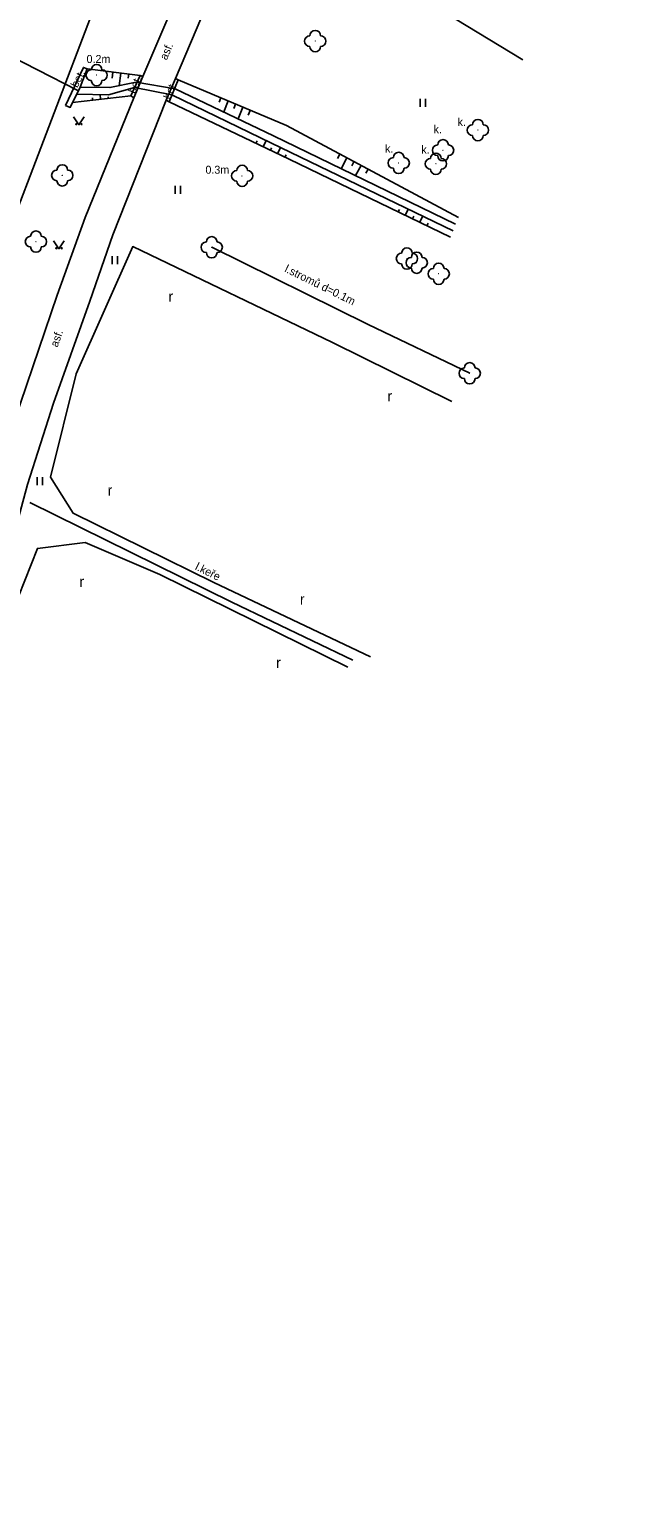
# Model space of a CAD drawing. Extents: x -544674 to -541478, y -1199076 to -1195527.
# Drawn here: x -543771.7 to -543714.9, y -1196778.9 to -1196641.1 of the extents above; entities that cross this region are included whole.
import ezdxf

# ---------------------------------------------------------------- set-up
doc = ezdxf.new("R2010")
doc.units = 0
for name, color, linetype in [('POMOC_POPIS', 7, 'Continuous'), ('ROZHRANÍ_PLOCH', 7, 'Continuous'), ('VÝŠKOPIS', 7, 'Continuous'), ('ZELEŇ', 7, 'Continuous'), ('ZN_DOPLŇKOVÉ', 7, 'Continuous'), ('ZN_KULTUR', 7, 'Continuous')]:
    doc.layers.add(name, color=color, linetype=linetype)

msp = doc.modelspace()

# ---------------------------------------------------------------- linework, layer by layer
at = {"layer": 'ROZHRANÍ_PLOCH'}
for points in [[(-543807.06, -1196806.28), (-543806.75, -1196807.49), (-543805.62, -1196808.57), (-543803.6, -1196809.36), (-543801.75, -1196808.81), (-543800.5, -1196806.91), (-543795.65, -1196782.4), (-543789.39, -1196750.31), (-543785.15, -1196728.76), (-543782.4, -1196714.76), (-543781.01, -1196708.01), (-543777.88, -1196694.39), (-543774.44, -1196682.01), (-543772.54, -1196676.07), (-543769.09, -1196665.96), (-543766.47, -1196658.69), (-543761.92, -1196647.47), (-543762.18, -1196647.29), (-543761.3, -1196645.37), (-543761.06, -1196645.47), (-543756.75, -1196635.37), (-543752.77, -1196625.68), (-543747.9, -1196614.82)], [(-543774.29, -1196661.75), (-543765.48, -1196638.63), (-543761.91, -1196630.37)], [(-543792.85, -1196784.15), (-543786.36, -1196750.19), (-543782.23, -1196728.89), (-543779.59, -1196715.45), (-543778.13, -1196707.91), (-543774.74, -1196694.16), (-543771.89, -1196683.71), (-543769.45, -1196676.08), (-543766.05, -1196666.53), (-543763.87, -1196660.3), (-543758.86, -1196647.68), (-543758.58, -1196647.85), (-543757.75, -1196645.78), (-543758, -1196645.66), (-543754.11, -1196636.49)], [(-543768.32, -1196648.19), (-543767.87, -1196648.36), (-543767.66, -1196647.89), (-543767.26, -1196647.12), (-543766.93, -1196646.48), (-543766.29, -1196644.75), (-543766.63, -1196644.61), (-543768.32, -1196648.19)], [(-543761.06, -1196645.47), (-543761.92, -1196647.47)], [(-543758.86, -1196647.68), (-543758, -1196645.66)]]:
    msp.add_lwpolyline(points, dxfattribs=at)
at = {"layer": 'VÝŠKOPIS'}
for points in [[(-543761.3, -1196645.37), (-543766.29, -1196644.75)], [(-543763.88, -1196645.05), (-543763.95, -1196645.63)], [(-543763.13, -1196645.14), (-543763.28, -1196646.33)], [(-543762.39, -1196645.23), (-543762.44, -1196645.61)], [(-543767.26, -1196647.12), (-543764.29, -1196647.18), (-543761.84, -1196646.51)], [(-543766.93, -1196646.48), (-543764.15, -1196646.51), (-543761.68, -1196646.01)], [(-543758.03, -1196646.62), (-543748.8, -1196651.02), (-543731.74, -1196659.32)], [(-543757.75, -1196645.78), (-543747.58, -1196650.07), (-543731.46, -1196658.68)], [(-543762.18, -1196647.29), (-543767.66, -1196647.89)], [(-543765.78, -1196647.68), (-543765.8, -1196647.47)], [(-543765.03, -1196647.6), (-543765.08, -1196647.16)], [(-543764.29, -1196647.52), (-543764.3, -1196647.38)], [(-543758.58, -1196647.85), (-543747.35, -1196653.23), (-543732.19, -1196660.53)], [(-543758.35, -1196647.18), (-543749, -1196651.72), (-543731.94, -1196659.92)], [(-543753.74, -1196647.47), (-543753.91, -1196647.87)], [(-543753.05, -1196647.76), (-543753.48, -1196648.79)], [(-543752.36, -1196648.05), (-543752.54, -1196648.48)], [(-543751.67, -1196648.35), (-543752.13, -1196649.43)], [(-543750.98, -1196648.64), (-543751.17, -1196649.09)], [(-543750.45, -1196651.74), (-543750.34, -1196651.51)], [(-543749.77, -1196652.07), (-543749.49, -1196651.48)], [(-543749.1, -1196652.39), (-543748.98, -1196652.16)], [(-543748.42, -1196652.72), (-543748.14, -1196652.13)], [(-543747.74, -1196653.04), (-543747.63, -1196652.81)], [(-543742.58, -1196652.74), (-543742.8, -1196653.16)], [(-543741.92, -1196653.09), (-543742.46, -1196654.11)], [(-543741.26, -1196653.45), (-543741.47, -1196653.84)], [(-543740.59, -1196653.8), (-543741.11, -1196654.76)], [(-543739.93, -1196654.15), (-543740.13, -1196654.53)], [(-543737.12, -1196658.16), (-543737, -1196657.92)], [(-543736.44, -1196658.48), (-543736.16, -1196657.89)], [(-543735.76, -1196658.81), (-543735.65, -1196658.57)], [(-543735.09, -1196659.13), (-543734.8, -1196658.54)], [(-543734.41, -1196659.46), (-543734.3, -1196659.22)]]:
    msp.add_lwpolyline(points, dxfattribs=at)
at = {"layer": 'ZELEŇ'}
for points in [[(-543725.42, -1196643.89), (-543741.06, -1196634.41), (-543746.4, -1196630.98), (-543747.4, -1196628.22), (-543742.23, -1196615), (-543735.35, -1196598.3), (-543723.28, -1196605.74), (-543714.93, -1196610.89)], [(-543739.72, -1196699.84), (-543754.4, -1196692.9), (-543767.61, -1196686.39), (-543769.73, -1196683.03), (-543767.31, -1196673.33), (-543762.01, -1196661.41), (-543743.28, -1196670.4), (-543732.09, -1196675.93)], [(-543730.4, -1196673.28), (-543739.94, -1196668.7), (-543754.6, -1196661.47)], [(-543741.36, -1196700.16), (-543752.71, -1196694.73), (-543771.65, -1196685.38)], [(-543781.96, -1196809.38), (-543794.69, -1196802.87), (-543792.17, -1196785.64), (-543785.53, -1196750.27), (-543781.37, -1196728.98), (-543778.66, -1196716.08), (-543776.59, -1196707.48), (-543772.72, -1196694.21), (-543770.96, -1196689.69), (-543766.47, -1196689.13), (-543759.47, -1196692.13), (-543741.82, -1196700.81)]]:
    msp.add_lwpolyline(points, dxfattribs=at)
for centre in [(-543744.89, -1196642.15), (-543765.4, -1196645.34), (-543729.63, -1196650.49), (-543732.9, -1196652.38), (-543737.06, -1196653.57), (-543733.57, -1196653.65), (-543768.62, -1196654.73), (-543751.75, -1196654.78), (-543771.09, -1196660.94), (-543754.6, -1196661.47), (-543736.29, -1196662.53), (-543735.37, -1196662.92), (-543733.31, -1196663.96), (-543730.4, -1196673.28)]:
    msp.add_circle(centre, 0.0005, dxfattribs=at)
for centre, start, end in [((-543744.89, -1196641.65), 0, 179.99999), ((-543745.39, -1196642.15), 89.99999, 269.99999), ((-543744.89, -1196642.65), 179.99999, 359.99999), ((-543744.39, -1196642.15), 270, 89.99999), ((-543765.9, -1196645.34), 89.99999, 269.99999), ((-543765.4, -1196644.84), 0, 179.99999), ((-543764.9, -1196645.34), 270, 89.99999), ((-543765.4, -1196645.84), 179.99999, 359.99999), ((-543729.63, -1196649.99), 0, 179.99999), ((-543730.13, -1196650.49), 89.99999, 269.99999), ((-543729.63, -1196650.99), 179.99999, 359.99999), ((-543729.13, -1196650.49), 270, 89.99999), ((-543733.4, -1196652.38), 89.99999, 269.99999), ((-543732.9, -1196651.88), 0, 179.99999), ((-543732.4, -1196652.38), 270, 89.99999), ((-543768.62, -1196654.23), 0, 179.99999), ((-543751.75, -1196654.28), 0, 179.99999), ((-543737.56, -1196653.57), 89.99999, 269.99999), ((-543737.06, -1196653.07), 0, 179.99999), ((-543736.56, -1196653.57), 270, 89.99999), ((-543734.07, -1196653.65), 89.99999, 269.99999), ((-543733.57, -1196653.15), 0, 179.99999), ((-543732.9, -1196652.88), 179.99999, 359.99999), ((-543733.07, -1196653.65), 270, 89.99999), ((-543769.12, -1196654.73), 89.99999, 269.99999), ((-543768.62, -1196655.23), 179.99999, 359.99999), ((-543768.12, -1196654.73), 270, 89.99999), ((-543752.25, -1196654.78), 89.99999, 269.99999), ((-543751.75, -1196655.28), 179.99999, 359.99999), ((-543751.25, -1196654.78), 270, 89.99999), ((-543737.06, -1196654.07), 179.99999, 359.99999), ((-543733.57, -1196654.15), 179.99999, 359.99999), ((-543771.59, -1196660.94), 89.99999, 269.99999), ((-543771.09, -1196660.44), 0, 179.99999), ((-543770.59, -1196660.94), 270, 89.99999), ((-543754.6, -1196660.97), 0, 179.99999), ((-543771.09, -1196661.44), 179.99999, 359.99999), ((-543755.1, -1196661.47), 89.99999, 269.99999), ((-543754.6, -1196661.97), 179.99999, 359.99999), ((-543754.1, -1196661.47), 270, 89.99999), ((-543736.79, -1196662.53), 89.99999, 269.99999), ((-543736.29, -1196662.03), 0, 179.99999), ((-543735.37, -1196662.42), 0, 179.99999), ((-543735.79, -1196662.53), 270, 89.99999), ((-543736.29, -1196663.03), 179.99999, 359.99999), ((-543735.87, -1196662.92), 89.99999, 269.99999), ((-543735.37, -1196663.42), 179.99999, 359.99999), ((-543734.87, -1196662.92), 270, 89.99999), ((-543733.81, -1196663.96), 89.99999, 269.99999), ((-543733.31, -1196663.46), 0, 179.99999), ((-543732.81, -1196663.96), 270, 89.99999), ((-543733.31, -1196664.46), 179.99999, 359.99999), ((-543730.9, -1196673.28), 89.99999, 269.99999), ((-543730.4, -1196672.78), 0, 179.99999), ((-543729.9, -1196673.28), 270, 89.99999), ((-543730.4, -1196673.78), 179.99999, 359.99999)]:
    msp.add_arc(centre, 0.5, start, end, dxfattribs=at)
at = {"layer": 'ZN_DOPLŇKOVÉ'}
for points in [[(-543767.16, -1196646.77), (-543774.76, -1196642.91)], [(-543761.84, -1196646.51), (-543758.35, -1196647.18)], [(-543761.68, -1196646.01), (-543758.03, -1196646.62)]]:
    msp.add_lwpolyline(points, dxfattribs=at)
at = {"layer": 'ZN_KULTUR'}
for p, q in [((-543735.06, -1196648.315), (-543735.06, -1196647.565)), ((-543734.56, -1196648.315), (-543734.56, -1196647.565)), ((-543758.03, -1196656.465), (-543758.03, -1196655.715)), ((-543757.53, -1196656.465), (-543757.53, -1196655.715)), ((-543763.94, -1196663.065), (-543763.94, -1196662.315)), ((-543763.44, -1196663.065), (-543763.44, -1196662.315)), ((-543770.97, -1196683.775), (-543770.97, -1196683.025)), ((-543770.47, -1196683.775), (-543770.47, -1196683.025))]:
    msp.add_line(p, q, dxfattribs=at)
for points in [[(-543767.56, -1196649.24), (-543767.06, -1196649.99), (-543766.56, -1196649.24)], [(-543769.43, -1196660.86), (-543768.93, -1196661.61), (-543768.43, -1196660.86)]]:
    msp.add_lwpolyline(points, dxfattribs=at)
for centre in [(-543767.31, -1196649.94), (-543766.81, -1196649.94), (-543769.18, -1196661.56), (-543768.68, -1196661.56)]:
    msp.add_circle(centre, 0.05, dxfattribs=at)

# ---------------------------------------------------------------- texts
at = {"layer": 'POMOC_POPIS'}
for s, rotation, p in [('asf.', 66.48377, (-543758.83, -1196643.99)), ('bet.', 62.72324, (-543767.21, -1196646.58)), ('bet.', 66.7323, (-543761.8, -1196647.14)), ('bet.', 68.15088, (-543758.47, -1196647.68)), ('asf.', 70.40321, (-543769.07, -1196670.89))]:
    msp.add_text(s, height=0.75, rotation=rotation, dxfattribs=at).set_placement(p)
at = {"layer": 'ZELEŇ'}
for s, p in [('0.2m', (-543766.34, -1196644.2)), ('k.', (-543731.54, -1196650.1)), ('k.', (-543733.79, -1196650.78)), ('k.', (-543738.34, -1196652.6)), ('k.', (-543734.94, -1196652.69)), ('0.3m', (-543755.19, -1196654.58))]:
    msp.add_text(s, height=0.75, dxfattribs=at).set_placement(p)
for s, rotation, p in [('l.stromů d=0.1m', 333.74847, (-543747.83, -1196663.74)), ('l.keře', 333.62694, (-543756.22, -1196691.65))]:
    msp.add_text(s, height=0.75, rotation=rotation, dxfattribs=at).set_placement(p)
at = {"layer": 'ZN_KULTUR'}
for p in [(-543758.658, -1196666.582), (-543738.118, -1196675.922), (-543764.368, -1196684.742), (-543767.018, -1196693.312), (-543746.328, -1196694.952), (-543748.558, -1196700.902)]:
    msp.add_text('r', height=1, dxfattribs=at).set_placement(p)

doc.saveas('drawing.dxf')
